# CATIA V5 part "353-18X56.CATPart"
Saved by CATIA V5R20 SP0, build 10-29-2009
Part number: 353-18X56
Definition: NONE
Nomenclature: 353-18X56
Source: Unknown
Description: 353-18X56
Bounding box of the stored display mesh (mm): x -5 to 51, y -15 to 15, z -15 to 15
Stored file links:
  C:\Users\Utente\Desktop\IO LAVORO\3D X SITO CF\X SITO\PLASTICA\353\353-18X56.CATPart
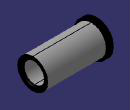
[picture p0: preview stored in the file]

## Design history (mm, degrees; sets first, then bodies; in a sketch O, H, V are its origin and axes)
Body1 "353-18X56" (main body)
  Solid1: solid without history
